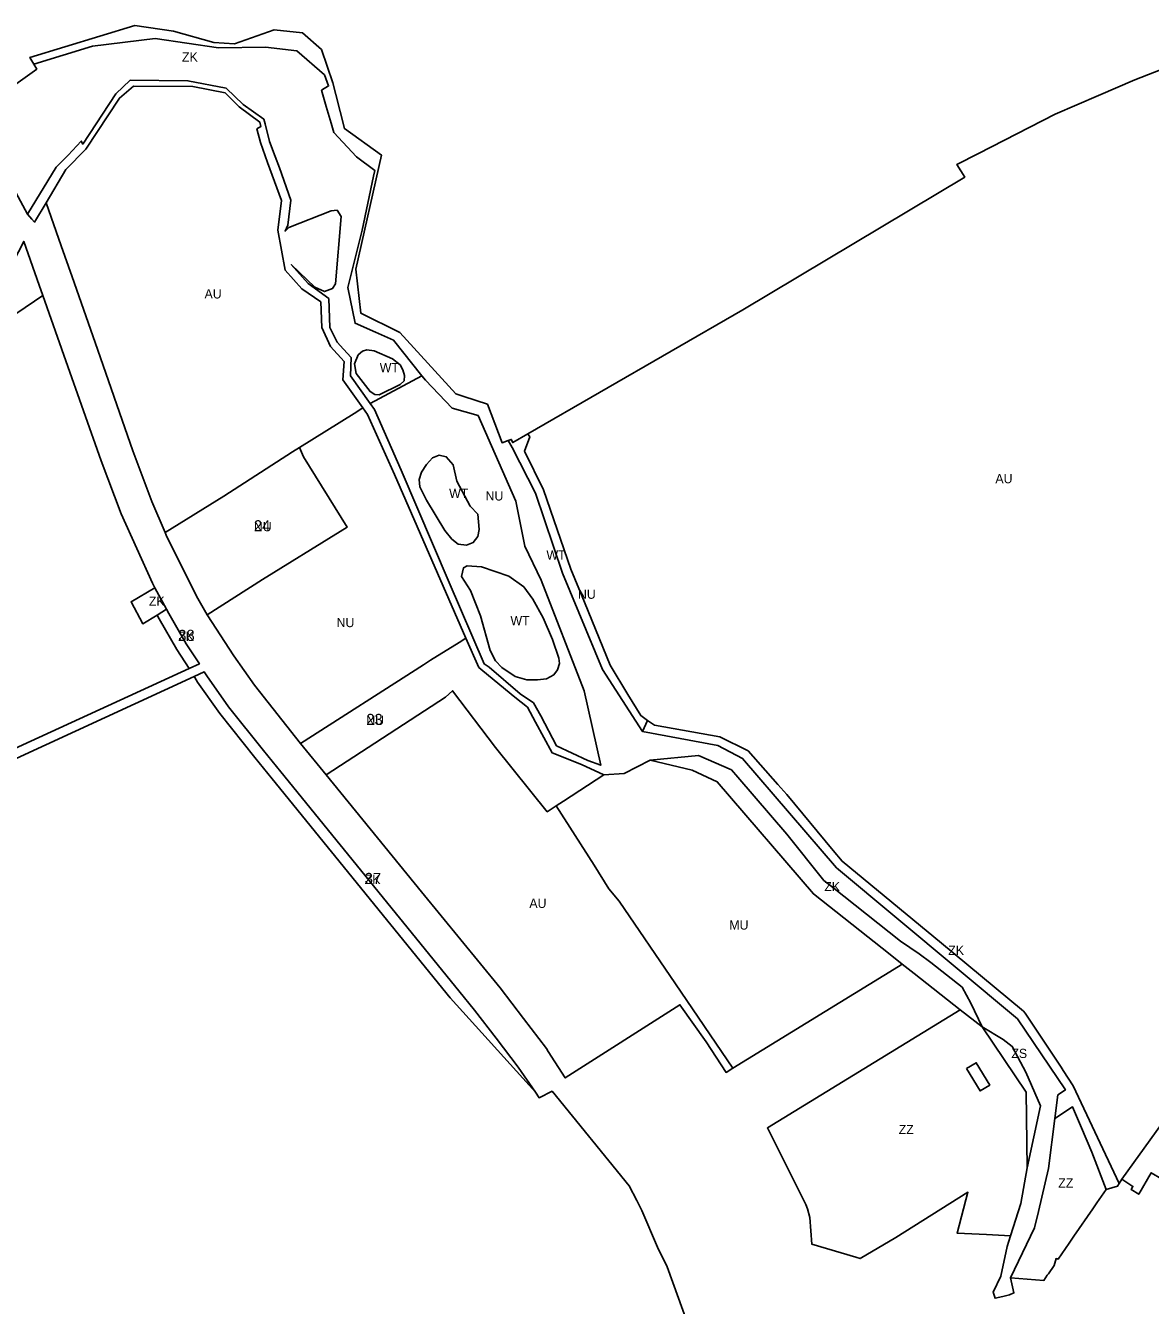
# Model space of a CAD drawing. Extents: x -522079 to -518833, y -1142398 to -1139961.
# Drawn here: x -521001 to -520390, y -1140787 to -1140093 of the extents above; entities that cross this region are included whole.
import ezdxf

# ---------------------------------------------------------------- set-up
doc = ezdxf.new("R2010")
doc.units = 0
for name, color, linetype in [('90640013', 7, 'Continuous'), ('90660013', 7, 'Continuous'), ('90670013', 7, 'Continuous'), ('90710013', 7, 'Continuous'), ('90710023', 7, 'Continuous'), ('90730013', 7, 'Continuous'), ('90730023', 7, 'Continuous'), ('90750013', 7, 'Continuous'), ('90830013', 7, 'Continuous'), ('ID_navrh', 7, 'Continuous')]:
    doc.layers.add(name, color=color, linetype=linetype)

msp = doc.modelspace()

# ---------------------------------------------------------------- linework, layer by layer
at = {"layer": '90640013'}
for points in [[(-520442.27, -1140685.74), (-520445.6, -1140712.87), (-520451.15, -1140736.24), (-520453.26, -1140745.12), (-520466.39, -1140772.32), (-520464.48, -1140780.47), (-520466.78, -1140781.53), (-520470.41, -1140782.37), (-520474.64, -1140783.36), (-520475.64, -1140780.08), (-520471.47, -1140771.35), (-520468.2, -1140755.18), (-520466.36, -1140749.44), (-520460.77, -1140732), (-520457.2, -1140712.56), (-520449.96, -1140678.96), (-520457.96, -1140660.67), (-520465.4, -1140646.75), (-520470.21, -1140643.01), (-520481.74, -1140636.06), (-520487.78, -1140623.27), (-520492.51, -1140614.6), (-520509.5, -1140601.29), (-520515.8, -1140596.49), (-520525.93, -1140589.59), (-520562.84, -1140560.36), (-520567.56, -1140556.74), (-520587.68, -1140531.64), (-520614.24, -1140500.69), (-520617.72, -1140496.63), (-520635.69, -1140488.94), (-520661.91, -1140491.42), (-520675.92, -1140498.77), (-520686.89, -1140499.45), (-520699.14, -1140493.81), (-520714.97, -1140487.48), (-520724, -1140470.78), (-520728.4, -1140462.65), (-520735.34, -1140457.3), (-520752.54, -1140443.09), (-520754.76, -1140441.12), (-520761.78, -1140425.25), (-520774.21, -1140397.13), (-520800.48, -1140336.51), (-520815.23, -1140303.96), (-520817.67, -1140300.36), (-520828.6, -1140285.19), (-520827.93, -1140275.18), (-520835.3, -1140267.04), (-520840.04, -1140256.81), (-520840.6, -1140242.88), (-520850.88, -1140235.71), (-520859.87, -1140225.61), (-520863.77, -1140204.01), (-520861.9, -1140187.8), (-520869.38, -1140167.25), (-520873.34, -1140156.37), (-520875.21, -1140149), (-520873.12, -1140147.75), (-520873.63, -1140145.32), (-520884.78, -1140137.14), (-520892.49, -1140129.42), (-520910.05, -1140126.02), (-520942.17, -1140125.91), (-520949.73, -1140132.35), (-520967.99, -1140160), (-520978.85, -1140171.05), (-520989.57, -1140189.1), (-520995.82, -1140199.62), (-520997.26, -1140198.03), (-520999.73, -1140195.29), (-520984.14, -1140169.84), (-520977.56, -1140163.28), (-520970.51, -1140155.67), (-520969.72, -1140157.28), (-520951.79, -1140130), (-520943.89, -1140122.58), (-520912.67, -1140122.89), (-520891.9, -1140126.87), (-520882.74, -1140135.78), (-520871.38, -1140143.8), (-520870.79, -1140146.36), (-520868.43, -1140155.94), (-520865.3, -1140164.1), (-520863, -1140170.11), (-520856.72, -1140187.75), (-520858.48, -1140201.26), (-520859.91, -1140204.51), (-520857.8, -1140202.58), (-520834.84, -1140193.48), (-520831.74, -1140193.15), (-520829.57, -1140196.57), (-520832.49, -1140233.14), (-520834.17, -1140235.54), (-520838.62, -1140237.3), (-520843.85, -1140234.81), (-520856.59, -1140222.67), (-520847.4, -1140232.82), (-520836.21, -1140241.05), (-520835.7, -1140256.78), (-520831.58, -1140264.76), (-520828.22, -1140268.46), (-520824.03, -1140273.06), (-520824.45, -1140283.03), (-520813.67, -1140297.99), (-520811.33, -1140301.33), (-520797.01, -1140334.21), (-520770.87, -1140395.08), (-520751.81, -1140439.25), (-520749.19, -1140441.04), (-520732.44, -1140455.44), (-520725.07, -1140460.42), (-520721.21, -1140467.33), (-520712.6, -1140483.62), (-520695.64, -1140491.57), (-520688.63, -1140494.17), (-520697.67, -1140453.81), (-520720.9, -1140393.9), (-520729.88, -1140375.38), (-520734.8, -1140350.95), (-520755.22, -1140304.57), (-520769.34, -1140300.61), (-520783.73, -1140285.25), (-520785.74, -1140282.9), (-520801.15, -1140263.64), (-520810.93, -1140259.32), (-520821.91, -1140254.48), (-520825.87, -1140235.03), (-520818.11, -1140203.91), (-520811.93, -1140174.77), (-520811.24, -1140171.54), (-520821.16, -1140164.16), (-520833.53, -1140151.04), (-520834.99, -1140146), (-520837.6, -1140136.97), (-520840.13, -1140128.04), (-520836.28, -1140125.74), (-520838.47, -1140119.76), (-520853.61, -1140106.69), (-520870.57, -1140104.77), (-520896.13, -1140105.14), (-520930.39, -1140100.03), (-520964.33, -1140104.24), (-520996.26, -1140113.95), (-520998.41, -1140110.24), (-520941.45, -1140093.01), (-520920.41, -1140096.1), (-520898.59, -1140102.13), (-520887.39, -1140102.82), (-520865.88, -1140095.27), (-520850.56, -1140096.88), (-520840.13, -1140106.03), (-520833.95, -1140124.09), (-520832.38, -1140130.38), (-520827.76, -1140148.83), (-520807.65, -1140163.22), (-520821.47, -1140225.09), (-520818.83, -1140248.97), (-520797.63, -1140259.52), (-520767.33, -1140292.73), (-520763.01, -1140294.16), (-520750.13, -1140298.42), (-520742.16, -1140319.24), (-520738.8, -1140318.04), (-520736.79, -1140321.94), (-520724.04, -1140346.68), (-520709.46, -1140390.03), (-520687.78, -1140442.24), (-520666, -1140475.86), (-520625.05, -1140483.49), (-520611.7, -1140490.5), (-520560.63, -1140549.81), (-520462.54, -1140631.68), (-520436.48, -1140670.33), (-520440.71, -1140673.04)], [(-520822.29, -1140276.46), (-520820.3, -1140271.64), (-520817.84, -1140269.53), (-520815.5, -1140268.8), (-520811.67, -1140269.37), (-520801.58, -1140273.72), (-520797.56, -1140277.1), (-520796.05, -1140279.66), (-520795.15, -1140282.87), (-520795.38, -1140285.61), (-520797.46, -1140287.61), (-520808.84, -1140293.29), (-520811.29, -1140293.11), (-520813.83, -1140291.57), (-520821.31, -1140281.75)], [(-520785.95, -1140335.16), (-520783.19, -1140331.06), (-520779.88, -1140327.47), (-520776.36, -1140326.07), (-520772.48, -1140326.88), (-520768.74, -1140331.28), (-520766.65, -1140340.21), (-520759.43, -1140353.7), (-520755.29, -1140358.03), (-520754.64, -1140366.29), (-520755.28, -1140370.09), (-520757.78, -1140373.33), (-520761.4, -1140374.89), (-520765.93, -1140374.29), (-520769.43, -1140371.66), (-520773.17, -1140366.91), (-520783.16, -1140350.46), (-520786.73, -1140343.23), (-520787.17, -1140339.26)], [(-520764.21, -1140391.88), (-520763.05, -1140387.08), (-520761.05, -1140386.08), (-520753.32, -1140386.65), (-520738.54, -1140391.69), (-520730.43, -1140397.36), (-520725.51, -1140404.14), (-520719.87, -1140414.3), (-520714.9, -1140426), (-520711.41, -1140436.09), (-520711.04, -1140439.09), (-520712.14, -1140442.41), (-520714.17, -1140445.14), (-520718.16, -1140447.28), (-520722.88, -1140447.92), (-520728.76, -1140447.85), (-520735.07, -1140445.99), (-520742.3, -1140441.21), (-520745.71, -1140437.58), (-520748.72, -1140432.03), (-520753.83, -1140413.22), (-520759.4, -1140399.48)]]:
    msp.add_lwpolyline(points, close=True, dxfattribs=at)
at = {"layer": '90660013'}
msp.add_lwpolyline([(-520481.74, -1140636.06), (-520470.21, -1140643.01), (-520465.4, -1140646.75), (-520457.96, -1140660.67), (-520449.96, -1140678.96), (-520457.2, -1140712.56), (-520457.81, -1140671.57)], close=True, dxfattribs=at)
at = {"layer": '90670013'}
for points in [[(-521071.39, -1140271.24), (-521083.46, -1140250.25), (-521079.08, -1140247.03), (-521070.02, -1140248.6), (-521067.28, -1140250.75), (-521047.85, -1140248.01), (-521021.33, -1140234.46), (-521010.26, -1140226.65), (-521001.72, -1140210.08), (-520993.36, -1140233.77), (-520991.34, -1140239.5), (-521029.36, -1140265.01), (-521042, -1140261.25), (-521054.61, -1140266.48), (-521065.28, -1140272.43), (-521069.26, -1140274.95)], [(-520481.74, -1140636.06), (-520457.81, -1140671.57), (-520457.2, -1140712.56), (-520460.77, -1140732), (-520466.36, -1140749.44), (-520479.24, -1140748.79), (-520495.27, -1140747.98), (-520489.4, -1140725.83), (-520528.59, -1140750.29), (-520547.81, -1140761.83), (-520550.23, -1140761.11), (-520574.04, -1140754.01), (-520575.25, -1140739.5), (-520576.44, -1140734.91), (-520577.29, -1140732.42), (-520580.64, -1140725.97), (-520586.97, -1140713.22), (-520598.21, -1140690.89), (-520493.55, -1140626.8)], [(-520490.13, -1140658.74), (-520482.81, -1140670.82), (-520477.53, -1140667.74), (-520484.85, -1140655.59)], [(-520371.84, -1140671.62), (-520364.42, -1140661.36), (-520369.41, -1140698.76), (-520375.15, -1140722.06), (-520384.29, -1140718.48), (-520389.9, -1140715.22), (-520396.68, -1140726.94), (-520400.9, -1140724.3), (-520399.85, -1140722.62), (-520405.96, -1140718.81), (-520371.84, -1140671.63)], [(-520442.27, -1140685.74), (-520432.59, -1140679.54), (-520427.81, -1140690.88), (-520422.23, -1140704.1), (-520414.39, -1140724.32), (-520418.13, -1140729.68), (-520419.44, -1140731.56), (-520421.72, -1140734.81), (-520431.9, -1140749.57), (-520434.44, -1140753.41), (-520440.36, -1140762.11), (-520441.56, -1140761.77), (-520442.65, -1140765.47), (-520442.66, -1140765.49), (-520445.76, -1140770.03), (-520446.34, -1140770.88), (-520448.2, -1140773.61), (-520466.39, -1140772.32), (-520453.26, -1140745.12), (-520451.15, -1140736.24), (-520445.6, -1140712.87)]]:
    msp.add_lwpolyline(points, close=True, dxfattribs=at)
at = {"layer": '90710013'}
msp.add_lwpolyline([(-521045.99, -1140153.16), (-520994.7, -1140116.62), (-520996.26, -1140113.95), (-520964.33, -1140104.24), (-520930.39, -1140100.03), (-520896.13, -1140105.14), (-520870.57, -1140104.77), (-520853.61, -1140106.69), (-520838.47, -1140119.76), (-520836.28, -1140125.74), (-520840.13, -1140128.04), (-520837.6, -1140136.97), (-520834.99, -1140146), (-520833.53, -1140151.04), (-520821.16, -1140164.16), (-520811.24, -1140171.54), (-520811.93, -1140174.77), (-520818.11, -1140203.91), (-520825.87, -1140235.03), (-520821.91, -1140254.48), (-520810.93, -1140259.32), (-520801.15, -1140263.64), (-520785.74, -1140282.9), (-520813.67, -1140297.99), (-520824.45, -1140283.03), (-520824.03, -1140273.06), (-520828.22, -1140268.46), (-520831.58, -1140264.76), (-520835.7, -1140256.78), (-520836.21, -1140241.05), (-520847.4, -1140232.82), (-520856.59, -1140222.67), (-520843.85, -1140234.81), (-520838.62, -1140237.3), (-520834.17, -1140235.54), (-520832.49, -1140233.14), (-520829.57, -1140196.57), (-520831.74, -1140193.15), (-520834.84, -1140193.48), (-520857.8, -1140202.58), (-520859.91, -1140204.51), (-520858.48, -1140201.26), (-520856.72, -1140187.75), (-520863, -1140170.11), (-520865.3, -1140164.1), (-520868.43, -1140155.94), (-520870.79, -1140146.36), (-520871.38, -1140143.8), (-520882.74, -1140135.78), (-520891.9, -1140126.87), (-520912.67, -1140122.89), (-520943.89, -1140122.58), (-520951.79, -1140130), (-520969.72, -1140157.28), (-520970.51, -1140155.67), (-520977.56, -1140163.28), (-520984.14, -1140169.84), (-520999.73, -1140195.29), (-521008.55, -1140178.79)], dxfattribs=at)
for points in [[(-520822.29, -1140276.46), (-520821.31, -1140281.75), (-520813.83, -1140291.57), (-520811.29, -1140293.11), (-520808.84, -1140293.29), (-520797.46, -1140287.61), (-520795.38, -1140285.61), (-520795.15, -1140282.87), (-520796.05, -1140279.66), (-520797.56, -1140277.1), (-520801.58, -1140273.72), (-520811.67, -1140269.37), (-520815.5, -1140268.8), (-520817.84, -1140269.53), (-520820.3, -1140271.64)], [(-520924.28, -1140409.64), (-520929.42, -1140412.75), (-520937.19, -1140417.44), (-520943.46, -1140405.56), (-520930.52, -1140398.04)], [(-520663.2, -1140469.86), (-520659.41, -1140472.47), (-520623.97, -1140478.75), (-520608.7, -1140486.32), (-520592.52, -1140504.62), (-520587.65, -1140510.13), (-520562.49, -1140540.48), (-520557.7, -1140546.26), (-520503.8, -1140590.78), (-520490.09, -1140602.11), (-520459.31, -1140627.54), (-520458.26, -1140628.64), (-520449.35, -1140642.33), (-520438.76, -1140658.07), (-520437.69, -1140659.73), (-520432.32, -1140668.06), (-520407.37, -1140721.08), (-520408.23, -1140722.45), (-520414.39, -1140724.32), (-520422.23, -1140704.1), (-520427.81, -1140690.88), (-520432.59, -1140679.54), (-520442.27, -1140685.74), (-520440.71, -1140673.04), (-520436.48, -1140670.33), (-520462.54, -1140631.68), (-520560.63, -1140549.81), (-520611.7, -1140490.5), (-520625.05, -1140483.49), (-520666, -1140475.86)], [(-520525.02, -1140602.15), (-520531.68, -1140596.93), (-520573.29, -1140563.98), (-520625.42, -1140503.23), (-520639.11, -1140496.92), (-520661.91, -1140491.42), (-520635.69, -1140488.94), (-520617.72, -1140496.63), (-520614.24, -1140500.69), (-520587.68, -1140531.64), (-520567.56, -1140556.74), (-520562.84, -1140560.36), (-520525.93, -1140589.59), (-520515.8, -1140596.49), (-520509.5, -1140601.29), (-520492.51, -1140614.6), (-520487.78, -1140623.27), (-520481.74, -1140636.06), (-520493.55, -1140626.8), (-520518.65, -1140607.14)]]:
    msp.add_lwpolyline(points, close=True, dxfattribs=at)
at = {"layer": '90710023'}
for points in [[(-520924.28, -1140409.64), (-520923.06, -1140411.9), (-520913.58, -1140428.33), (-520906.37, -1140439.12), (-520911.89, -1140441.66), (-520918.68, -1140431.5), (-520928.3, -1140414.82), (-520929.42, -1140412.75)], [(-520909.31, -1140446.06), (-520903.84, -1140443.54), (-520902.4, -1140445.74), (-520890.58, -1140462.46), (-520871.65, -1140486.28), (-520862.22, -1140497.87), (-520765.71, -1140616.57), (-520757.18, -1140627.06), (-520745.42, -1140642.26), (-520733.42, -1140657.97), (-520724.12, -1140671.61), (-520770.37, -1140620.36), (-520866.87, -1140501.66), (-520876.33, -1140490.04), (-520895.38, -1140466.06), (-520907.36, -1140449.12), (-520908.96, -1140446.68)]]:
    msp.add_lwpolyline(points, close=True, dxfattribs=at)
at = {"layer": '90730013'}
for points in [[(-520785.74, -1140282.9), (-520783.73, -1140285.25), (-520769.34, -1140300.61), (-520755.22, -1140304.57), (-520734.8, -1140350.95), (-520729.88, -1140375.38), (-520720.9, -1140393.9), (-520697.67, -1140453.81), (-520688.63, -1140494.17), (-520695.64, -1140491.57), (-520712.6, -1140483.62), (-520721.21, -1140467.33), (-520725.07, -1140460.42), (-520732.44, -1140455.44), (-520749.19, -1140441.04), (-520751.81, -1140439.25), (-520770.87, -1140395.08), (-520797.01, -1140334.21), (-520811.33, -1140301.33), (-520813.67, -1140297.99)], [(-520817.67, -1140300.36), (-520815.23, -1140303.96), (-520800.48, -1140336.51), (-520774.21, -1140397.13), (-520761.78, -1140425.25), (-520765.49, -1140427.57), (-520781.06, -1140437.3), (-520784.75, -1140439.67), (-520851.49, -1140482.48), (-520876.46, -1140450.75), (-520887.82, -1140434.78), (-520902.19, -1140412.67), (-520872.15, -1140393.54), (-520830.07, -1140367.42), (-520826.19, -1140365.01), (-520849.95, -1140326.96), (-520852.13, -1140321.93), (-520822.46, -1140303.46)], [(-520663.2, -1140469.86), (-520666, -1140475.86), (-520687.78, -1140442.24), (-520709.46, -1140390.03), (-520724.04, -1140346.68), (-520736.79, -1140321.94), (-520738.8, -1140318.04), (-520737.2, -1140317.47), (-520736.37, -1140319.22), (-520728.21, -1140314.51), (-520727.12, -1140316.09), (-520729.96, -1140323.84), (-520719.64, -1140344.89), (-520704.93, -1140387.92), (-520697.54, -1140405.82), (-520683.48, -1140439.85), (-520673.87, -1140455.8), (-520666.98, -1140467.24)], [(-520785.95, -1140335.16), (-520787.17, -1140339.26), (-520786.73, -1140343.23), (-520783.16, -1140350.46), (-520773.17, -1140366.91), (-520769.43, -1140371.66), (-520765.93, -1140374.29), (-520761.4, -1140374.89), (-520757.78, -1140373.33), (-520755.28, -1140370.09), (-520754.64, -1140366.29), (-520755.29, -1140358.03), (-520759.43, -1140353.7), (-520766.65, -1140340.21), (-520768.74, -1140331.28), (-520772.48, -1140326.88), (-520776.36, -1140326.07), (-520779.88, -1140327.47), (-520783.19, -1140331.06)], [(-520764.21, -1140391.88), (-520759.4, -1140399.48), (-520753.83, -1140413.22), (-520748.72, -1140432.03), (-520745.71, -1140437.58), (-520742.3, -1140441.21), (-520735.07, -1140445.99), (-520728.76, -1140447.85), (-520722.88, -1140447.92), (-520718.16, -1140447.28), (-520714.17, -1140445.14), (-520712.14, -1140442.41), (-520711.04, -1140439.09), (-520711.41, -1140436.09), (-520714.9, -1140426), (-520719.87, -1140414.3), (-520725.51, -1140404.14), (-520730.43, -1140397.36), (-520738.54, -1140391.69), (-520753.32, -1140386.65), (-520761.05, -1140386.08), (-520763.05, -1140387.08)]]:
    msp.add_lwpolyline(points, close=True, dxfattribs=at)
at = {"layer": '90730023'}
for points in [[(-520925.04, -1140368.05), (-520893.13, -1140348.26), (-520855.89, -1140324.19), (-520852.13, -1140321.93), (-520849.95, -1140326.96), (-520826.19, -1140365.01), (-520830.07, -1140367.42), (-520872.15, -1140393.54), (-520902.19, -1140412.67), (-520907.24, -1140403.74), (-520915.77, -1140387.04), (-520924.44, -1140369.44)], [(-520761.78, -1140425.25), (-520754.76, -1140441.12), (-520752.54, -1140443.09), (-520735.34, -1140457.3), (-520728.4, -1140462.65), (-520724, -1140470.78), (-520714.97, -1140487.48), (-520699.14, -1140493.81), (-520686.89, -1140499.45), (-520708.82, -1140513.67), (-520712.75, -1140516.21), (-520717.71, -1140519.42), (-520745.68, -1140484.57), (-520769.04, -1140453.82), (-520772.84, -1140457.31), (-520837.71, -1140499.35), (-520851.49, -1140482.48), (-520784.75, -1140439.67), (-520781.06, -1140437.3), (-520765.49, -1140427.57)]]:
    msp.add_lwpolyline(points, close=True, dxfattribs=at)
at = {"layer": '90750013'}
for points in [[(-520371.84, -1140671.63), (-520405.96, -1140718.81), (-520407.37, -1140721.08), (-520432.32, -1140668.06), (-520437.69, -1140659.73), (-520438.76, -1140658.07), (-520449.35, -1140642.33), (-520458.26, -1140628.64), (-520459.31, -1140627.54), (-520490.09, -1140602.11), (-520503.8, -1140590.78), (-520557.7, -1140546.26), (-520562.49, -1140540.48), (-520587.65, -1140510.13), (-520592.52, -1140504.62), (-520608.7, -1140486.32), (-520623.97, -1140478.75), (-520659.41, -1140472.47), (-520663.2, -1140469.86), (-520666.98, -1140467.24), (-520673.87, -1140455.8), (-520683.48, -1140439.85), (-520697.54, -1140405.82), (-520704.93, -1140387.92), (-520719.64, -1140344.89), (-520729.96, -1140323.84), (-520727.12, -1140316.09), (-520728.21, -1140314.51), (-520611.62, -1140247.2), (-520491.09, -1140175.17), (-520495.34, -1140168.3), (-520483.64, -1140162.33), (-520442, -1140141.08), (-520418.53, -1140130.92), (-520398.93, -1140122.43), (-520359.48, -1140107)], [(-521029.36, -1140265.01), (-520991.34, -1140239.5), (-520978.89, -1140274.79), (-520959.74, -1140329.07), (-520948.85, -1140357.77), (-520931.92, -1140395.43), (-520930.52, -1140398.04), (-520943.46, -1140405.56), (-520937.19, -1140417.44), (-520929.42, -1140412.75), (-520928.3, -1140414.82), (-520918.68, -1140431.5), (-520911.89, -1140441.66), (-521031.07, -1140496.4)], [(-521038.29, -1140505.39), (-520909.31, -1140446.06), (-520908.96, -1140446.68), (-520907.36, -1140449.12), (-520895.38, -1140466.06), (-520876.33, -1140490.04), (-520866.87, -1140501.66), (-520770.37, -1140620.36), (-520724.12, -1140671.61), (-520722.11, -1140674.56), (-520715.02, -1140671.04), (-520673.31, -1140722.41), (-520669.12, -1140730.36), (-520666.3, -1140735.71), (-520657.82, -1140755.57), (-520652.69, -1140766.32), (-520641.11, -1140798.37)]]:
    msp.add_lwpolyline(points, dxfattribs=at)
for points in [[(-520925.04, -1140368.05), (-520932.27, -1140351.12), (-520942.5, -1140323.7), (-520963.03, -1140264.99), (-520975.5, -1140229.32), (-520981.4, -1140212.45), (-520989.57, -1140189.1), (-520978.85, -1140171.05), (-520967.99, -1140160), (-520949.73, -1140132.35), (-520942.17, -1140125.91), (-520910.05, -1140126.02), (-520892.49, -1140129.42), (-520884.78, -1140137.14), (-520873.63, -1140145.32), (-520873.12, -1140147.75), (-520875.21, -1140149), (-520873.34, -1140156.37), (-520869.38, -1140167.25), (-520861.9, -1140187.8), (-520863.77, -1140204.01), (-520859.87, -1140225.61), (-520850.88, -1140235.71), (-520840.6, -1140242.88), (-520840.04, -1140256.81), (-520835.3, -1140267.04), (-520827.93, -1140275.18), (-520828.6, -1140285.19), (-520817.67, -1140300.36), (-520822.46, -1140303.46), (-520852.13, -1140321.93), (-520855.89, -1140324.19), (-520893.13, -1140348.26)], [(-520631.48, -1140644.23), (-520645.69, -1140624.14), (-520707.94, -1140663.79), (-520717.09, -1140649.55), (-520718.15, -1140647.9), (-520730.64, -1140631.58), (-520743.28, -1140615.01), (-520785.9, -1140562.81), (-520813.81, -1140528.62), (-520837.71, -1140499.35), (-520772.84, -1140457.31), (-520769.04, -1140453.82), (-520745.68, -1140484.57), (-520717.71, -1140519.42), (-520712.75, -1140516.21), (-520692.27, -1140548.47), (-520684.19, -1140561.2), (-520678.73, -1140568), (-520648.02, -1140612.72), (-520617.05, -1140658.61), (-520620.66, -1140660.83)]]:
    msp.add_lwpolyline(points, close=True, dxfattribs=at)
at = {"layer": '90830013'}
msp.add_lwpolyline([(-520525.02, -1140602.15), (-520527.15, -1140603.46), (-520617.05, -1140658.61), (-520648.02, -1140612.72), (-520678.73, -1140568), (-520684.19, -1140561.2), (-520692.27, -1140548.47), (-520712.75, -1140516.21), (-520708.82, -1140513.67), (-520686.89, -1140499.45), (-520675.92, -1140498.77), (-520661.91, -1140491.42), (-520639.11, -1140496.92), (-520625.42, -1140503.23), (-520573.29, -1140563.98), (-520531.68, -1140596.93)], close=True, dxfattribs=at)

# ---------------------------------------------------------------- texts
at = {"layer": '90640013'}
for p in [(-520808.551, -1140281.045), (-520770.905, -1140349.26), (-520737.625, -1140418.315)]:
    msp.add_text('WT', height=5, rotation=360, dxfattribs=at).set_placement(p)
msp.add_text('WT', height=5, dxfattribs=at).set_placement((-520718.105, -1140382.717))
at = {"layer": '90660013'}
msp.add_text('ZS', height=5, rotation=360, dxfattribs=at).set_placement((-520465.85, -1140653.02))
at = {"layer": '90670013'}
for p in [(-520526.979, -1140694.315), (-520440.39, -1140723.319)]:
    msp.add_text('ZZ', height=5, rotation=360, dxfattribs=at).set_placement(p)
at = {"layer": '90710013'}
for rotation, p in [(360, (-520915.865, -1140112.527)), (0, (-520933.806, -1140407.74)), (360, (-520567.349, -1140562.5)), (0, (-520500.074, -1140597.09))]:
    msp.add_text('ZK', height=5, rotation=rotation, dxfattribs=at).set_placement(p)
at = {"layer": '90710023'}
for rotation, p in [(0, (-520917.895, -1140426.763)), (360, (-520816.715, -1140558.595))]:
    msp.add_text('ZK', height=5, rotation=rotation, dxfattribs=at).set_placement(p)
at = {"layer": '90730013'}
for p in [(-520751.15, -1140350.602), (-520701, -1140403.921), (-520831.985, -1140419.289)]:
    msp.add_text('NU', height=5, rotation=0, dxfattribs=at).set_placement(p)
at = {"layer": '90730023'}
for p in [(-520876.854, -1140367.3), (-520815.849, -1140472.335)]:
    msp.add_text('NU', height=5, rotation=0, dxfattribs=at).set_placement(p)
at = {"layer": '90750013'}
for rotation, p in [(0, (-520903.62, -1140241.015)), (360, (-520474.506, -1140341.25)), (360, (-520727.38, -1140571.606))]:
    msp.add_text('AU', height=5, rotation=rotation, dxfattribs=at).set_placement(p)
at = {"layer": '90830013'}
msp.add_text('MU', height=5, rotation=360, dxfattribs=at).set_placement((-520618.885, -1140583.368))
at = {"layer": 'ID_navrh'}
for s, rotation, p in [('24', 0, (-520876.854, -1140367.3)), ('38', 0, (-520917.895, -1140426.763)), ('23', 0, (-520815.849, -1140472.335)), ('37', 360, (-520816.715, -1140558.595))]:
    msp.add_text(s, height=6, rotation=rotation, dxfattribs=at).set_placement(p)

doc.saveas('drawing.dxf')
